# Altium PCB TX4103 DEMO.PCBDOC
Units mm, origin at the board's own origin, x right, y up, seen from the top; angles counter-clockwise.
Board outline 40.31 x 30.31 mm, 2 copper layers (TopLayer, BottomLayer); 9 components, 6 nets, 26 pads, 13 vias.
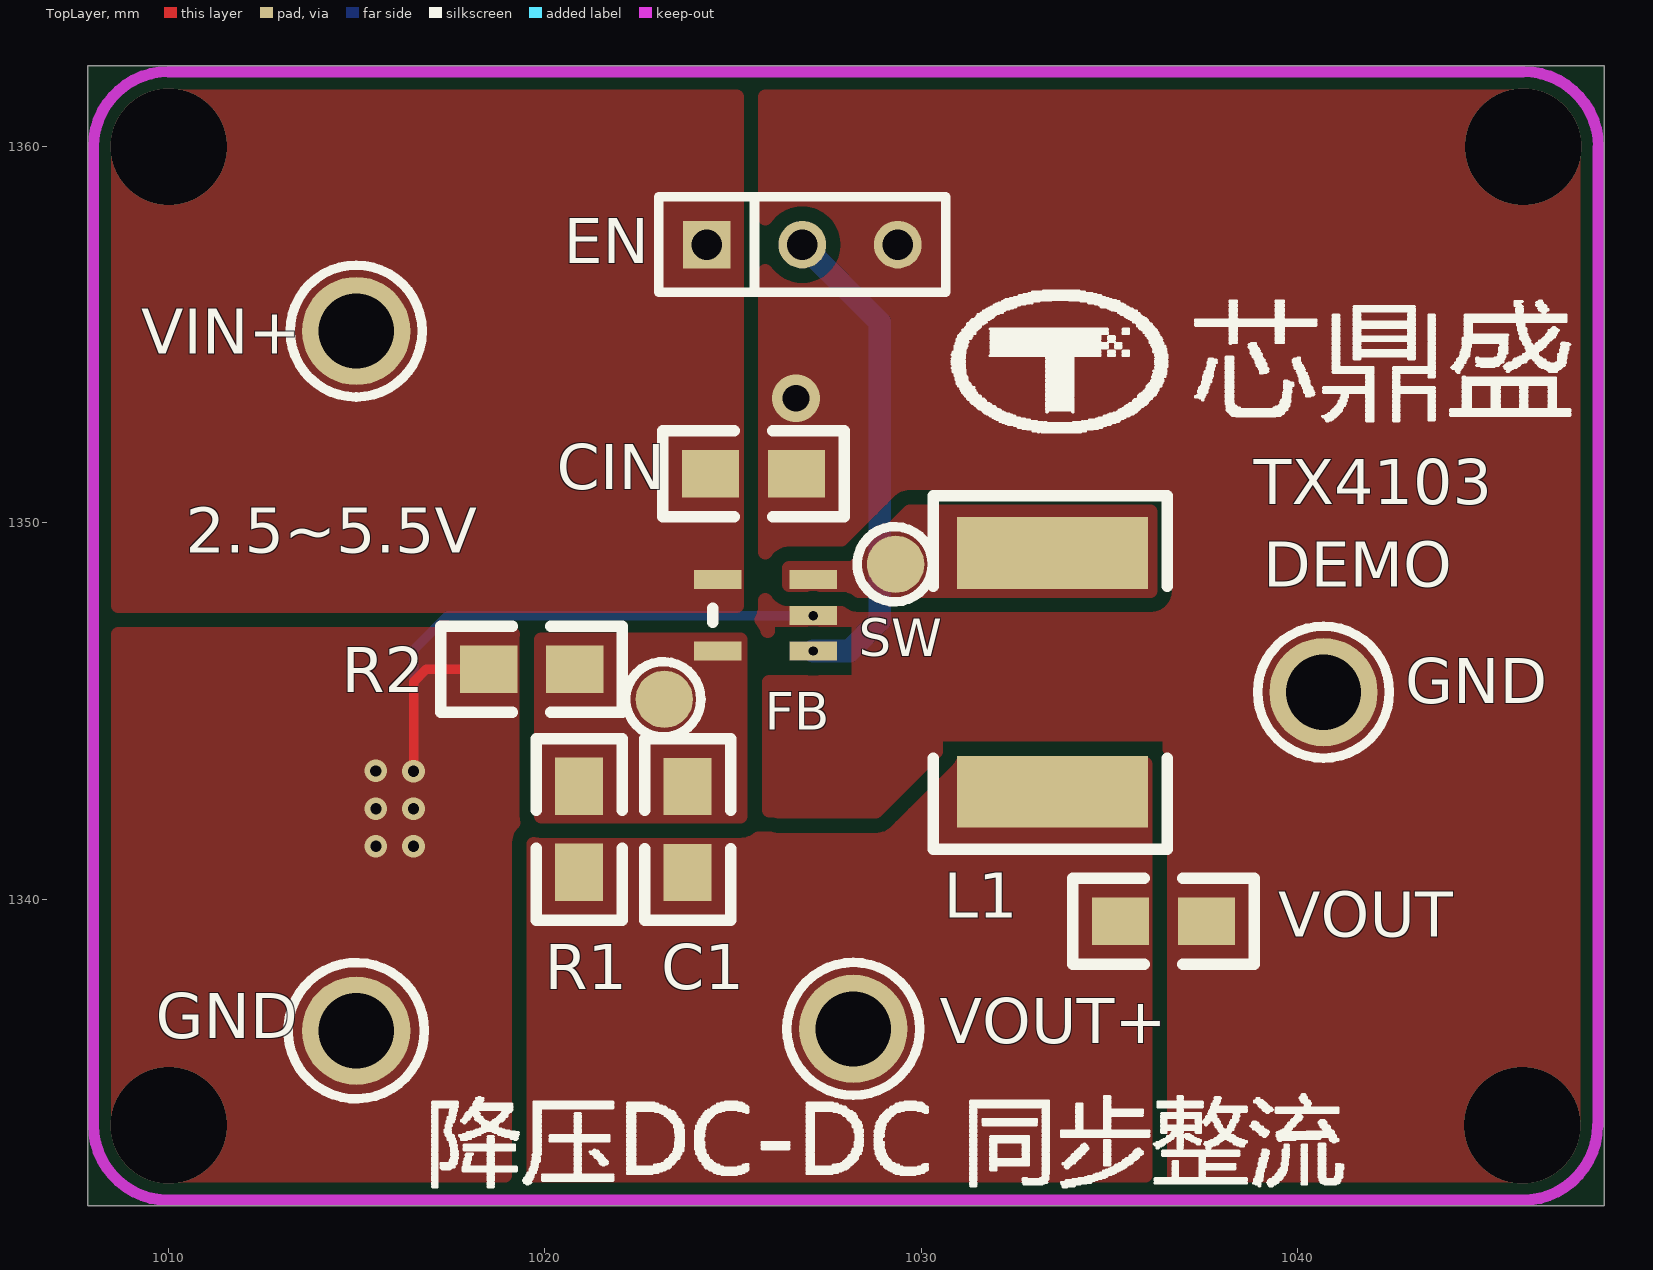
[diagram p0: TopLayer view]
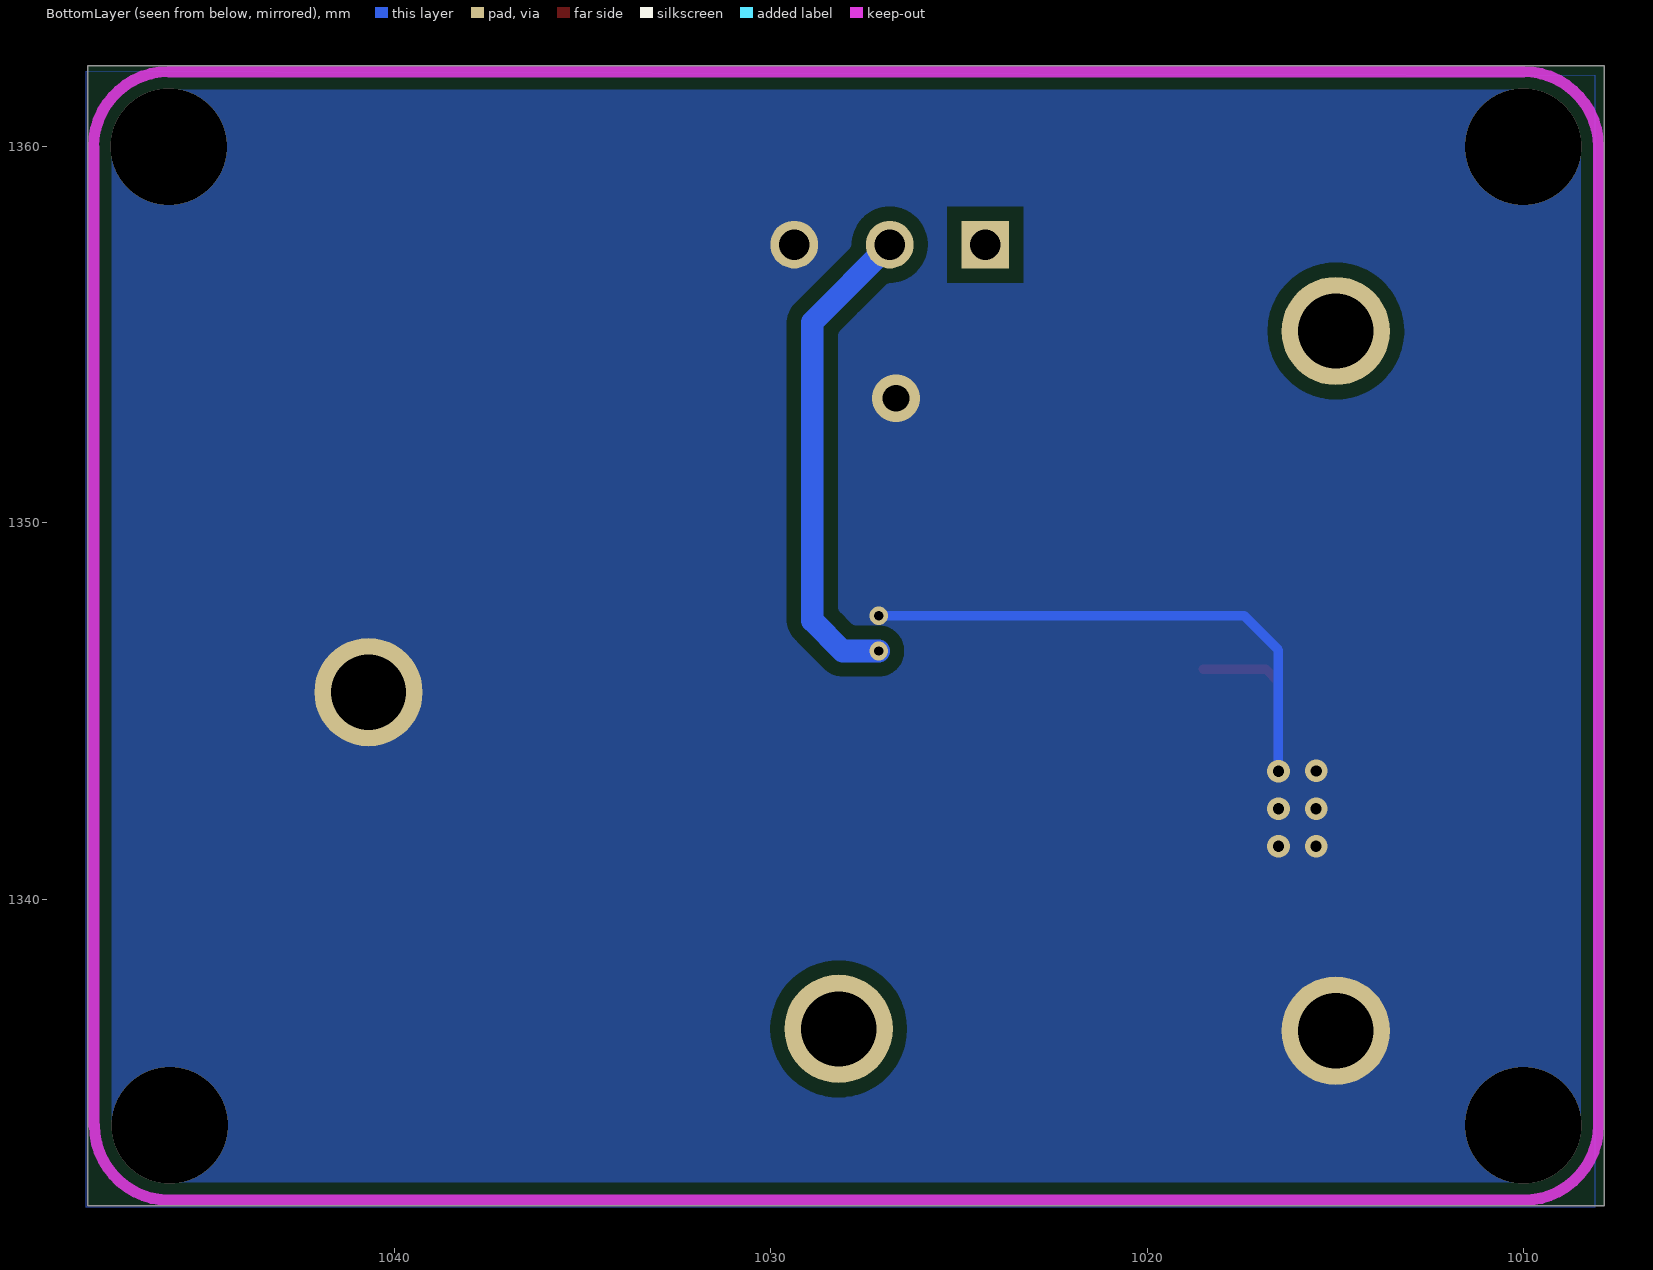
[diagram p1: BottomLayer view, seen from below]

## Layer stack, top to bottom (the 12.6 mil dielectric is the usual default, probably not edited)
TopLayer: signal copper 0.0356
Dielectric: dielectric 0.32, FR-4, Dk 4.8
BottomLayer: signal copper 0.0356

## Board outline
1007.85,1331.84 1048.16,1331.84 1048.16,1362.15 1007.85,1362.15

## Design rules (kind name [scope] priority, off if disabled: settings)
Clearance [All] p1: gap=0.381
PolygonConnect [All] p1: connectstyle=Relief reliefconductorwidth=0.254 reliefentries=4 polygonreliefangle="90 Angle"
RoutingPriority [All] p1: routingpriority=4
RoutingVias [All] p1: holewidth=0.508 width=1.27 viastyle="Through Hole" minholewidth=0.711 minwidth=1.27 maxholewidth=0.711 maxwidth=1.27
SilkscreenOverComponentPads [All] p1: minsilkscreentomaskgap=0.254
SolderMaskExpansion [All] p1: expansion=0.102
TestPointUsage [All] p1: valid=0 allowmultiple=FALSE
Testpoint [All] p1: side=15 testpointundercomponent=TRUE minsize=1.016 maxsize=2.54 preferedsize=1.524 minholesize=0.508 maxholesize=1.016 preferedholesize=0.813 testpointgrid=0.025 style=1023 order=0123456789
Width [All] p1: maxlimit=2 minlimit=0.1 preferedwidth=0.254
22 further rules are at their usual default settings.

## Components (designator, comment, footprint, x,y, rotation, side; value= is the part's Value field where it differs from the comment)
C1 "" 0805 1023.8,1340.7 r90 top
CIN "" 0805 1024.4,1351.3 r0 top
EN "" SIP3 1024.3,1357.4 r0 top
L1 "" 2220 1033.5,1349.2 r270 top
R1 "" 0805 1020.9,1343 r270 top
R2 "" 0805 1018.5,1346.1 r0 top
VOUT "" 0805 1035.3,1339.4 r0 top
? "Comment" LOGO 1033.7,1354.8 r0 top
? "" SOT-25 1024.598,1348.503 r270 top

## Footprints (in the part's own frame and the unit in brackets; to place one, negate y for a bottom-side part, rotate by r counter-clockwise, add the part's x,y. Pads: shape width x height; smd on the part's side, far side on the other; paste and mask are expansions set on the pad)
0805 [mil]
  rect 60x50 smd: 1(0.15,0.31) 2(90.15,0.31)
  silkscreen extent -50,-45 140,45
2220 [mm]
  rect 1.905x5.08 smd: 1(0,0) 2(6.35,0)
  silkscreen extent -1.52,-3.18 7.87,3.05
LOGO [mm]
  silkscreen extent -2.88,-2.39 13.56,1.37
SIP3 [mil]
  rect 50x50 hole 32: 1(0.1,-0.12)
  round 50 hole 32: 2(100.1,-0.12) 3(200.1,-0.12)
  silkscreen extent -50,-50 250,50
SOT-25 [mil]
  rect 20x50 smd: 1(75.18,99.89) 2(0.18,99.89) 3(38.18,99.89) 4(75.18,-0.11) 5(0.18,-0.11)
  silkscreen extent 30,-5 45,-5

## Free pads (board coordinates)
  round 1.524 smd: 2(1023.175,1345.311) 2(1029.325,1348.9)
  round 2.88 hole 2: 6(1014.984,1355.1) 7(1028.2,1336.548) 8(1014.984,1336.5) 9(1040.7,1345.5)

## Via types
v1: diameter 0.6, hole 0.3, TopLayer to BottomLayer, 6 vias
v2: diameter 3.1, hole 3.1, TopLayer to BottomLayer, 4 vias
v3: diameter 0.5, hole 0.25, TopLayer to BottomLayer, 2 vias
v4: diameter 1.27, hole 0.711, TopLayer to BottomLayer, 1 vias

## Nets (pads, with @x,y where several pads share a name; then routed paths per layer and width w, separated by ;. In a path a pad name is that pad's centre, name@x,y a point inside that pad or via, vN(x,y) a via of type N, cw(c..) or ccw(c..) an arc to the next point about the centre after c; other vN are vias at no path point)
EN: ?.1 EN.2 | length 12.9
  BottomLayer w0.6: EN.2 1028.9,1355.339 1028.9,1347.4 1028.093,1346.593 v3(1027.135,1346.593)
FB: ?.4 C1.2 R1.1 R2.2
GND: ?.3 CIN.2 EN.3 pad.8 pad.9 R2.1 VOUT.2 | length 18.7
  TopLayer w0.254: v1(1016.508,1343.4) 1016.508,1345.775 1016.841,1346.108 R2.1
  BottomLayer w0.254: v1(1016.508,1343.4) 1016.508,1346.618 1017.423,1347.533 v3(1027.135,1347.533)
  other v1: 1015.508,1341.4 1016.508,1341.4 1015.508,1342.4 1016.508,1342.4 1015.5,1343.406
  other v4: 1026.675,1353.312
SW: ?.2 L1.1 pad.2@1029.325,1348.9
VIN: ?.5 CIN.1 EN.1 pad.6
VOUT: C1.1 L1.2 pad.7 R1.2 VOUT.1
copper on no net:
  other v2: 1010,1333.99 1045.985,1333.99 1010,1360 1046.01,1360

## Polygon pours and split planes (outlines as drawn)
GND on TopLayer "TopLayer-GND" (hatched 90Degree grid 0 track 0.381, remove dead copper, pour order 1000): 1024.7,1362.7 1024.7,1331.7 1048.7,1331.7 1048.7,1362.5
GND on TopLayer "TopLayer-GND 2" (hatched 90Degree grid 0 track 0.381, remove dead copper, pour order 1002): 1008,1349.7 1021.5,1349.7 1021.5,1329.4 1007.4,1329.4
VIN on TopLayer "TopLayer-VIN" (hatched 90Degree grid 0 track 0.381, remove dead copper, pour order 1003): 1025.1,1361.8 1025.1,1347.8 1007,1347.8 1007,1362.2
VOUT on TopLayer "TopLayer-VOUT" (hatched 90Degree grid 0 track 0.381, remove dead copper, pour order 1004): 1019.7,1332.1 1019.7,1341.6 1029.1,1341.6 1031.1,1343.6 1036,1343.6 1036,1332.1
FB on TopLayer "TopLayer-FB" (hatched 90Degree grid 0 track 0.381, remove dead copper, pour order 1005): 1019.9,1346.8 1019.9,1342.2 1025.2,1342.2 1025.2,1346.9 1019.9,1346.9
SW on TopLayer "TopLayer-SW" (hatched 90Degree grid 0 track 0.381, remove dead copper, pour order 1006): 1026.5,1348.2 1036.1,1348.2 1036.1,1350.3 1029.7,1350.3 1028.2,1348.8 1026.5,1348.8
GND on BottomLayer "BottomLayer-GND" (hatched 90Degree grid 0 track 0.381, remove dead copper, pour order 1007): 1008.1,1361.9 1008.1,1331.8 1048.2,1331.8 1048.2,1362

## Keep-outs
KeepOutLayer:
  lines w0.3: 1008,1359.99 1008,1333.99 ccw(c1010,1333.99) 1010,1331.99 1046,1331.99 ; 1008,1360 cw(c1010,1360) 1010,1362 ; 1010,1361.99 1046,1361.99 ; 1045.985,1331.99 ccw(c1045.985,1333.99) 1047.985,1333.99 ; 1046.01,1362 cw(c1046.01,1360) 1048.01,1360 ; 1048,1333.99 1048,1359.99

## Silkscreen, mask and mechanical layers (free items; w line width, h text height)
TopOverlay:
  drawing of 1482 lines, arcs and shapes, not listed
  text "VIN+" at 1009.269,1354.5 h1.2
  text "TX4103" at 1038.85,1350.5 h1.2
  text "2.5~5.5V" at 1010.45,1349.2 h1.2
  text "DEMO" at 1039.1,1348.3 h1.2
  text "SW" at 1028.341,1346.454 h1
  text "GND" at 1042.875,1345.2 h1.2
  text "FB" at 1025.85,1344.5 h1
  text "GND" at 1009.65,1336.3 h1.2
  text "VOUT+" at 1030.5,1336.167 h1.2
